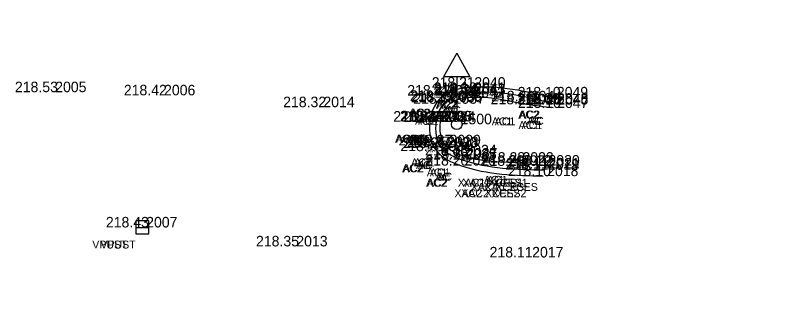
# Model space of a CAD drawing. Extents: x -471047 to -470889, y -1102859 to -1102000.
# Drawn here: x -470949.12 to -470919.5, y -1102389.32 to -1102378.65 of the extents above; entities that cross this region are included whole.
import ezdxf

# ---------------------------------------------------------------- set-up
doc = ezdxf.new("R2010")
doc.units = 0
for name, color, linetype in [('Vrstva 1', 7, 'Continuous'), ('Vrstva 19', 7, 'Continuous'), ('Vrstva 25', 7, 'Continuous'), ('Vrstva 34', 7, 'Continuous'), ('Vrstva 35', 7, 'Continuous'), ('Vrstva 36', 7, 'Continuous'), ('Vrstva 38', 7, 'Continuous'), ('Vrstva 5', 7, 'Continuous'), ('Vrstva 7', 7, 'Continuous'), ('Vrstva 8', 7, 'Continuous')]:
    doc.layers.add(name, color=color, linetype=linetype)

msp = doc.modelspace()

# ---------------------------------------------------------------- linework, layer by layer
at = {"layer": 'Vrstva 1'}
for points in [[(-471040.344, -1102858.385), (-471031.676, -1102846.187), (-471026.357, -1102838.629), (-471023.212, -1102833.975), (-471019.21, -1102827.465), (-471016.861, -1102823.272), (-471013.099, -1102815.912), (-471010.824, -1102810.955), (-471007.329, -1102802.292), (-471005.34, -1102796.515), (-471002.842, -1102787.838), (-471001.3, -1102780.997), (-471000.19, -1102774.713), (-470999.247, -1102768.204), (-470998.794, -1102764.784), (-470997.199, -1102751.812), (-470994.899, -1102732.807), (-470992.551, -1102713.262), (-470990.326, -1102694.887), (-470988.122, -1102676.57), (-470985.812, -1102657.305), (-470983.537, -1102638.407), (-470981.386, -1102620.622), (-470979.843, -1102608.014), (-470976.377, -1102579.253), (-470972.945, -1102550.69), (-470970.475, -1102530.206), (-470967.905, -1102508.801), (-470965.053, -1102485.131), (-470962.734, -1102465.9), (-470960.173, -1102444.812), (-470957.795, -1102425.103), (-470954.965, -1102401.839), (-470953.834, -1102392.574), (-470952.33, -1102379.985), (-470950.744, -1102366.853), (-470948.978, -1102352.106), (-470947.037, -1102335.844), (-470944.949, -1102318.462), (-470944.013, -1102310.745), (-470942.39, -1102297.267), (-470939.519, -1102273.45), (-470937.593, -1102257.43), (-470936.064, -1102244.81), (-470934.114, -1102228.634), (-470931.621, -1102207.856), (-470929.536, -1102190.857), (-470926.572, -1102166.31), (-470924.91, -1102152.663), (-470923.413, -1102140.333), (-470921.923, -1102127.669), (-470921.155, -1102120.084), (-470920.446, -1102109.574), (-470919.912, -1102099.137), (-470919.63, -1102088.981), (-470919.523, -1102081.193), (-470919.563, -1102070.395), (-470919.714, -1102064.236), (-470920.134, -1102054.704), (-470920.462, -1102047.615), (-470920.599, -1102044.52), (-470920.743, -1102041.873), (-470921.125, -1102034.455), (-470921.774, -1102030.337), (-470922.418, -1102027.787), (-470923.734, -1102023.93), (-470924.872, -1102021.434), (-470926.752, -1102018.182), (-470927.953, -1102016.45), (-470929.616, -1102014.424), (-470932.252, -1102011.756), (-470935.111, -1102009.425), (-470938.391, -1102007.371), (-470942.651, -1102005.401)], [(-471041.328, -1102857.18), (-471032.144, -1102844.242), (-471027.583, -1102837.763), (-471024.388, -1102833.028), (-471020.451, -1102826.6), (-471018.089, -1102822.378), (-471014.542, -1102815.445), (-471012.233, -1102810.418), (-471009.247, -1102803.108), (-471006.795, -1102796.098), (-471004.315, -1102787.532), (-471002.782, -1102780.723), (-471001.674, -1102774.458), (-471000.75, -1102768.095), (-471000.28, -1102764.601), (-470998.692, -1102751.741), (-470996.378, -1102732.635), (-470994.028, -1102713.058), (-470991.808, -1102694.749), (-470989.616, -1102676.447), (-470987.284, -1102657.013), (-470985.031, -1102638.272), (-470982.87, -1102620.431), (-470981.334, -1102607.933), (-470977.881, -1102579.263), (-470974.429, -1102550.492), (-470971.964, -1102530.054), (-470969.391, -1102508.607), (-470966.54, -1102484.984), (-470964.231, -1102465.853), (-470961.679, -1102444.752), (-470959.304, -1102425.078), (-470956.455, -1102401.634), (-470955.339, -1102392.489), (-470953.812, -1102379.71), (-470952.249, -1102366.808), (-470950.479, -1102352.023), (-470948.536, -1102335.868), (-470946.426, -1102318.233), (-470945.493, -1102310.531), (-470943.864, -1102297.013), (-470940.984, -1102273.071), (-470939.078, -1102257.195), (-470937.559, -1102244.684), (-470935.592, -1102228.353), (-470933.101, -1102207.653), (-470931.011, -1102190.57), (-470928.046, -1102166.021), (-470926.409, -1102152.578), (-470924.898, -1102140.121), (-470923.427, -1102127.544), (-470922.647, -1102119.826), (-470921.919, -1102109.229), (-470921.42, -1102099.134), (-470921.127, -1102089.016), (-470921.023, -1102081.453), (-470921.061, -1102070.468), (-470921.209, -1102064.314), (-470921.666, -1102053.966), (-470922.156, -1102043.345), (-470922.299, -1102039.934), (-470922.637, -1102034.36), (-470923.091, -1102031.241), (-470923.847, -1102028.247), (-470925.083, -1102024.594), (-470926.222, -1102022.086), (-470928.04, -1102018.943), (-470929.138, -1102017.357), (-470930.929, -1102015.175), (-470933.062, -1102013.049), (-470936.379, -1102010.368), (-470939.169, -1102008.662), (-470942.899, -1102006.906), (-470945.661, -1102005.908)], [(-471043.557, -1102855.955), (-471035.129, -1102844.026), (-471029.872, -1102836.499), (-471026.577, -1102831.578), (-471022.675, -1102825.415), (-471020.123, -1102821.053), (-471016.667, -1102814.59), (-471014.208, -1102809.45), (-471011.177, -1102802.451), (-471008.55, -1102795.333), (-471006.082, -1102787.209), (-471004.464, -1102780.376), (-471003.265, -1102774.167), (-471002.327, -1102767.948), (-471001.636, -1102762.527), (-471000.297, -1102751.605), (-470997.959, -1102732.524), (-470995.602, -1102712.802), (-470993.412, -1102694.623), (-470991.21, -1102676.17), (-470988.891, -1102656.857), (-470986.625, -1102638.083), (-470984.455, -1102620.195), (-470982.936, -1102607.733), (-470979.497, -1102579.223), (-470976.023, -1102550.279), (-470973.554, -1102529.822), (-470970.991, -1102508.497), (-470968.146, -1102484.787), (-470965.835, -1102465.72), (-470963.284, -1102444.529), (-470960.91, -1102424.942), (-470958.043, -1102401.343), (-470956.946, -1102392.356), (-470955.396, -1102379.408), (-470953.851, -1102366.636), (-470952.049, -1102351.733), (-470950.124, -1102335.611), (-470948.034, -1102318.083), (-470947.094, -1102310.328), (-470945.421, -1102296.51), (-470942.58, -1102272.848), (-470940.675, -1102256.948), (-470939.176, -1102244.526), (-470937.187, -1102228.174), (-470934.708, -1102207.467), (-470932.621, -1102190.433), (-470929.634, -1102165.778), (-470928.004, -1102152.415), (-470926.45, -1102139.595), (-470925.003, -1102127.418), (-470924.249, -1102119.695), (-470923.515, -1102109.093), (-470923.018, -1102099.069), (-470922.711, -1102088.911), (-470922.643, -1102081.356), (-470922.797, -1102070.414), (-470923.018, -1102064.454), (-470923.52, -1102053.203), (-470923.823, -1102047.529), (-470924.123, -1102041.506), (-470924.462, -1102037.486), (-470924.934, -1102031.904), (-470925.664, -1102028.672), (-470926.771, -1102025.506), (-470927.959, -1102022.914), (-470929.674, -1102020.028), (-470930.76, -1102018.498), (-470932.447, -1102016.478), (-470935.215, -1102013.816), (-470937.644, -1102011.98), (-470940.381, -1102010.371), (-470943.968, -1102008.669), (-470947.145, -1102007.524), (-470950.874, -1102006.74)], [(-471044.756, -1102855.056), (-471036.376, -1102843.177), (-471031.167, -1102835.741), (-471027.859, -1102830.8), (-471023.934, -1102824.593), (-471021.43, -1102820.312), (-471018.011, -1102813.91), (-471015.536, -1102808.75), (-471012.578, -1102801.897), (-471009.95, -1102794.77), (-471007.561, -1102786.914), (-471005.936, -1102780.074), (-471004.727, -1102773.818), (-471003.828, -1102767.827), (-471003.121, -1102762.345), (-471001.787, -1102751.467), (-470999.446, -1102732.348), (-470997.073, -1102712.539), (-470994.902, -1102694.521), (-470992.696, -1102676.023), (-470990.376, -1102656.68), (-470988.131, -1102638.071), (-470985.947, -1102620.018), (-470984.417, -1102607.512), (-470980.993, -1102579.08), (-470977.514, -1102550.137), (-470975.048, -1102529.649), (-470972.488, -1102508.37), (-470969.618, -1102484.508), (-470967.34, -1102465.669), (-470964.767, -1102444.39), (-470962.402, -1102424.781), (-470959.534, -1102401.193), (-470958.432, -1102392.151), (-470956.883, -1102379.208), (-470955.335, -1102366.424), (-470953.535, -1102351.506), (-470951.606, -1102335.399), (-470949.519, -1102317.94), (-470948.575, -1102310.159), (-470946.889, -1102296.144), (-470944.056, -1102272.618), (-470942.139, -1102256.659), (-470940.657, -1102244.341), (-470938.638, -1102227.749), (-470936.19, -1102207.298), (-470934.102, -1102190.255), (-470931.124, -1102165.639), (-470929.492, -1102152.254), (-470927.915, -1102139.252), (-470926.46, -1102127.103), (-470925.74, -1102119.604), (-470925.012, -1102108.913), (-470924.523, -1102099.054), (-470924.217, -1102088.866), (-470924.148, -1102081.334), (-470924.301, -1102070.391), (-470924.518, -1102064.43), (-470924.97, -1102054.435), (-470925.588, -1102041.569), (-470925.963, -1102035.313), (-470926.405, -1102032.225), (-470927.078, -1102029.198), (-470928.123, -1102026.148), (-470929.318, -1102023.558), (-470930.84, -1102020.97), (-470931.868, -1102019.515), (-470933.443, -1102017.605), (-470936.26, -1102014.885), (-470938.429, -1102013.255), (-470941.213, -1102011.639), (-470944.847, -1102009.927), (-470947.723, -1102008.912), (-470951.444, -1102008.161), (-470954.511, -1102007.931), (-470957.895, -1102008.041)]]:
    msp.add_spline(points, degree=3, dxfattribs=at)
at = {"layer": 'Vrstva 19'}
for p, q in [((-470932.337, -1102380.082), (-470932.837, -1102380.982)), ((-470932.337, -1102380.082), (-470931.837, -1102380.982)), ((-470931.837, -1102380.982), (-470932.837, -1102380.982)), ((-470932.337, -1102380.982), (-470932.337, -1102382.582))]:
    msp.add_line(p, q, dxfattribs=at)
msp.add_circle((-470932.337, -1102382.782), 0.2, dxfattribs=at)
at = {"layer": 'Vrstva 25'}
for p, q in [((-470944.547, -1102386.449), (-470944.547, -1102386.949)), ((-470944.047, -1102386.449), (-470944.547, -1102386.449)), ((-470944.047, -1102386.949), (-470944.047, -1102386.449)), ((-470944.547, -1102386.699), (-470944.047, -1102386.699)), ((-470944.547, -1102386.949), (-470944.047, -1102386.949))]:
    msp.add_line(p, q, dxfattribs=at)
at = {"layer": 'Vrstva 34'}
for p, q in [((-470931.82, -1102381.39), (-470931.82, -1102381.39)), ((-470947.76, -1102381.56), (-470947.76, -1102381.56)), ((-470943.62, -1102381.68), (-470943.62, -1102381.68)), ((-470932.84, -1102381.69), (-470932.84, -1102381.69)), ((-470931.85, -1102381.77), (-470931.85, -1102381.77)), ((-470931.83, -1102381.59), (-470931.83, -1102381.59)), ((-470931.82, -1102381.64), (-470931.82, -1102381.64)), ((-470928.68, -1102381.76), (-470928.68, -1102381.76)), ((-470937.56, -1102382.13), (-470937.56, -1102382.13)), ((-470932.73, -1102381.89), (-470932.73, -1102381.89)), ((-470932.7, -1102381.94), (-470932.7, -1102381.94)), ((-470932.61, -1102382), (-470932.61, -1102382)), ((-470929.69, -1102382.02), (-470929.69, -1102382.02)), ((-470929.67, -1102381.91), (-470929.67, -1102381.91)), ((-470928.67, -1102382), (-470928.67, -1102382)), ((-470928.67, -1102382.03), (-470928.67, -1102382.03)), ((-470928.67, -1102382.16), (-470928.67, -1102382.16)), ((-470933.37, -1102382.68), (-470933.37, -1102382.68)), ((-470933.12, -1102382.67), (-470933.12, -1102382.67)), ((-470933.08, -1102382.67), (-470933.08, -1102382.67)), ((-470932.97, -1102382.69), (-470932.97, -1102382.69)), ((-470932.34, -1102382.78), (-470932.34, -1102382.78)), ((-470932.76, -1102383.58), (-470932.76, -1102383.58)), ((-470933.1, -1102383.8), (-470933.1, -1102383.8)), ((-470932.9, -1102383.68), (-470932.9, -1102383.68)), ((-470932.85, -1102383.65), (-470932.85, -1102383.65)), ((-470932.16, -1102383.96), (-470932.16, -1102383.96)), ((-470932.16, -1102384.12), (-470932.16, -1102384.12)), ((-470932.13, -1102384.08), (-470932.13, -1102384.08)), ((-470932.19, -1102384.35), (-470932.19, -1102384.35)), ((-470930.01, -1102384.36), (-470930.01, -1102384.36)), ((-470929.99, -1102384.24), (-470929.99, -1102384.24)), ((-470929, -1102384.35), (-470929, -1102384.35)), ((-470929, -1102384.46), (-470929, -1102384.46)), ((-470929.05, -1102384.75), (-470929.05, -1102384.75)), ((-470929.02, -1102384.51), (-470929.02, -1102384.51)), ((-470944.3, -1102386.7), (-470944.3, -1102386.7)), ((-470938.59, -1102387.42), (-470938.59, -1102387.42)), ((-470929.62, -1102387.84), (-470929.62, -1102387.84))]:
    msp.add_line(p, q, dxfattribs=at)
at = {"layer": 'Vrstva 5'}
msp.add_spline([(-470928.681, -1102381.762), (-470931.817, -1102381.385), (-470932.845, -1102381.689), (-470933.368, -1102382.683), (-470933.099, -1102383.8), (-470932.192, -1102384.345), (-470929.05, -1102384.746)], degree=3, dxfattribs=at)
at = {"layer": 'Vrstva 7'}
msp.add_spline([(-470928.67, -1102382.16), (-470929.686, -1102382.022), (-470931.85, -1102381.768), (-470932.611, -1102382.003), (-470932.972, -1102382.688), (-470932.764, -1102383.583), (-470932.159, -1102383.955), (-470929.992, -1102384.243), (-470929.004, -1102384.349)], degree=3, dxfattribs=at)
at = {"layer": 'Vrstva 8'}
msp.add_spline([(-470928.675, -1102382.002), (-470931.833, -1102381.591), (-470932.726, -1102381.889), (-470933.124, -1102382.667), (-470932.904, -1102383.682), (-470932.165, -1102384.115), (-470929.016, -1102384.515)], degree=3, dxfattribs=at)

# ---------------------------------------------------------------- texts
at = {"layer": 'Vrstva 35'}
for s, p in [('AC2', (-470933.136, -1102382.19)), ('AC2', (-470933.095, -1102382.19)), ('AC', (-470932.819, -1102382.39)), ('AC', (-470932.744, -1102382.39)), ('AC2', (-470934.156, -1102382.49)), ('AC2', (-470934.115, -1102382.49)), ('AC', (-470933.719, -1102382.69)), ('AC', (-470933.644, -1102382.69)), ('AC1', (-470933.167, -1102382.57)), ('AC1', (-470933.05, -1102382.57)), ('AC2', (-470929.996, -1102382.56)), ('AC2', (-470929.955, -1102382.56)), ('AC1', (-470933.927, -1102382.8)), ('AC1', (-470933.81, -1102382.8)), ('AC1', (-470931.007, -1102382.82)), ('AC1', (-470930.89, -1102382.82)), ('AC1', (-470929.987, -1102382.96)), ('AC1', (-470929.87, -1102382.96)), ('AC', (-470929.659, -1102382.8)), ('AC', (-470929.584, -1102382.8)), ('AC2', (-470934.686, -1102383.48)), ('AC2', (-470934.645, -1102383.48)), ('ZNACKA', (-470934.54, -1102383.58)), ('AC1', (-470934.287, -1102383.49)), ('AC1', (-470934.17, -1102383.49)), ('ZNACKA', (-470934.154, -1102383.58)), ('AC', (-470934.109, -1102383.47)), ('AC', (-470934.034, -1102383.47)), ('AC1', (-470934.077, -1102384.38)), ('AC1', (-470933.96, -1102384.38)), ('AC', (-470933.889, -1102384.48)), ('AC', (-470933.814, -1102384.48)), ('AC2', (-470934.416, -1102384.6)), ('AC2', (-470934.375, -1102384.6)), ('AC1', (-470933.477, -1102384.76)), ('AC1', (-470933.36, -1102384.76)), ('AC', (-470933.149, -1102384.92)), ('AC', (-470933.074, -1102384.92)), ('AC1', (-470931.307, -1102385.04)), ('AC1', (-470931.19, -1102385.04)), ('AC2', (-470933.506, -1102385.15)), ('AC2', (-470933.465, -1102385.15)), ('XAC1 XCES1', (-470932.3, -1102385.15)), ('XAC1 XCES1', (-470932.117, -1102385.15)), ('XAC XCES', (-470931.809, -1102385.31)), ('XAC XCES', (-470931.284, -1102385.31)), ('XAC2 XCES2', (-470932.425, -1102385.55)), ('XAC2 XCES2', (-470932.166, -1102385.55)), ('VPUST', (-470946.2, -1102387.5)), ('VPUST', (-470945.889, -1102387.5))]:
    msp.add_text(s, height=0.3, dxfattribs=at).set_placement(p)
at = {"layer": 'Vrstva 36'}
for s, p in [(' 2005', (-470947.76, -1102381.56)), (' 2041', (-470931.83, -1102381.59)), (' 2040', (-470931.82, -1102381.39)), (' 2043', (-470931.82, -1102381.64)), (' 2006', (-470943.62, -1102381.68)), (' 2039', (-470932.84, -1102381.69)), (' 2038', (-470932.73, -1102381.89)), (' 2036', (-470932.7, -1102381.94)), (' 2042', (-470931.85, -1102381.77)), (' 2044', (-470929.67, -1102381.91)), (' 2049', (-470928.68, -1102381.76)), (' 2014', (-470937.56, -1102382.13)), (' 2037', (-470932.61, -1102382)), (' 2046', (-470929.69, -1102382.02)), (' 2048', (-470928.67, -1102382)), (' 2045', (-470928.67, -1102382.03)), (' 2047', (-470928.67, -1102382.16)), (' 2032', (-470933.37, -1102382.68)), (' 2033', (-470933.12, -1102382.67)), (' 2035', (-470933.08, -1102382.67)), (' 2034', (-470932.97, -1102382.69)), (' 1500', (-470932.34, -1102382.78)), (' 2030', (-470932.9, -1102383.68)), (' 2028', (-470932.85, -1102383.65)), (' 2029', (-470932.76, -1102383.58)), (' 2031', (-470933.1, -1102383.8)), (' 2024', (-470932.16, -1102383.96)), (' 2025', (-470932.16, -1102384.12)), (' 2027', (-470932.13, -1102384.08)), (' 2023', (-470929.99, -1102384.24)), (' 2026', (-470932.19, -1102384.35)), (' 2022', (-470930.01, -1102384.36)), (' 2019', (-470929.02, -1102384.51)), (' 2020', (-470929, -1102384.35)), (' 2021', (-470929, -1102384.46)), (' 2018', (-470929.05, -1102384.75)), (' 2007', (-470944.3, -1102386.7)), (' 2013', (-470938.59, -1102387.42)), (' 2017', (-470929.62, -1102387.84))]:
    msp.add_text(s, height=0.4, dxfattribs=at).set_placement(p)
at = {"layer": 'Vrstva 38'}
for s, p in [('218.53 ', (-470949.143, -1102381.56)), ('218.21 ', (-470933.29, -1102381.39)), ('218.18 ', (-470933.214, -1102381.59)), ('218.34 ', (-470933.202, -1102381.64)), ('218.42 ', (-470945.001, -1102381.68)), ('218.22 ', (-470934.221, -1102381.69)), ('218.19 ', (-470934.114, -1102381.89)), ('218.37 ', (-470934.083, -1102381.94)), ('218.34 ', (-470933.232, -1102381.77)), ('218.26 ', (-470931.03, -1102381.91)), ('218.10 ', (-470930.023, -1102381.76)), ('218.32 ', (-470938.941, -1102382.13)), ('218.37 ', (-470933.993, -1102382)), ('218.26 ', (-470931.05, -1102382.02)), ('218.09 ', (-470930.054, -1102382)), ('218.10 ', (-470930.013, -1102382.03)), ('218.10 ', (-470930.013, -1102382.16)), ('218.24 ', (-470934.752, -1102382.68)), ('218.24 ', (-470934.502, -1102382.67)), ('218.38 ', (-470934.464, -1102382.67)), ('218.38 ', (-470934.354, -1102382.69)), ('218.21 ', (-470934.37, -1102383.68)), ('218.37 ', (-470934.233, -1102383.65)), ('218.37 ', (-470934.143, -1102383.58)), ('218.23 ', (-470934.483, -1102383.8)), ('218.35 ', (-470933.544, -1102383.96)), ('218.19 ', (-470933.544, -1102384.12)), ('218.35 ', (-470933.514, -1102384.08)), ('218.28 ', (-470931.374, -1102384.24)), ('218.20 ', (-470933.533, -1102384.35)), ('218.28 ', (-470931.394, -1102384.36)), ('218.11 ', (-470930.49, -1102384.51)), ('218.11 ', (-470930.47, -1102384.46)), ('218.12 ', (-470930.381, -1102384.35)), ('218.10 ', (-470930.393, -1102384.75)), ('218.43 ', (-470945.683, -1102386.7)), ('218.35 ', (-470939.974, -1102387.42)), ('218.11 ', (-470931.09, -1102387.84))]:
    msp.add_text(s, height=0.4, dxfattribs=at).set_placement(p)

doc.saveas('drawing.dxf')
